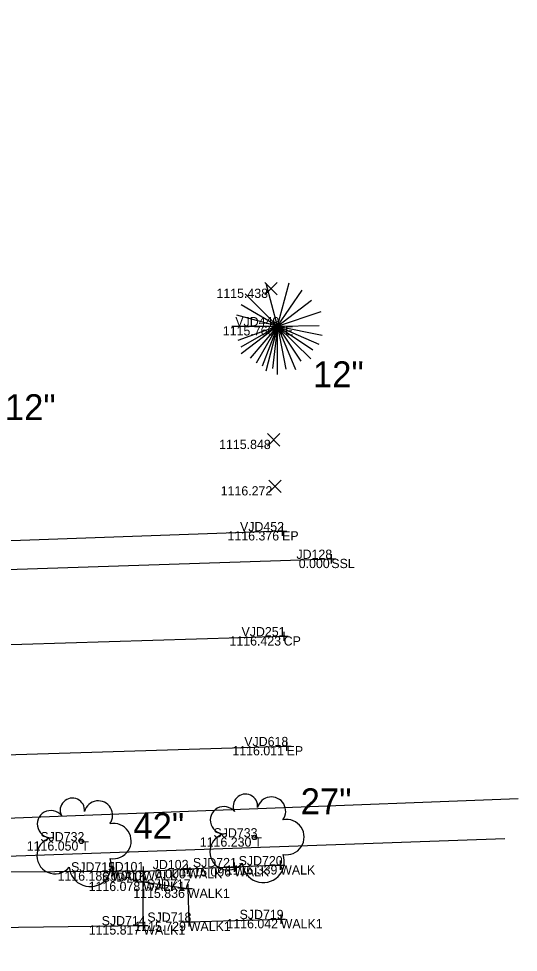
# Model space of a CAD drawing. Extents: x 1629915 to 1630675, y 484401 to 484601.
# Drawn here: x 1630621.1 to 1630675.1, y 484466.8 to 484567.8 of the extents above; entities that cross this region are included whole.
import ezdxf

# ---------------------------------------------------------------- set-up
doc = ezdxf.new("R2010")
doc.units = 0
for name, color, linetype in [('BR_X_Sub_Foot_Object', 7, 'Continuous'), ('PV_X_COP', 7, 'Continuous'), ('PV_X_EOP', 7, 'Continuous'), ('PV_X_Walk', 7, 'Continuous'), ('SV_X_Random_Point', 7, 'Continuous'), ('SV_X_Shot_Marker', 7, 'Continuous'), ('SV_X_Text_Comment', 7, 'Continuous'), ('SV_X_Text_Elevation', 7, 'Continuous'), ('SV_X_Text_Name', 7, 'Continuous'), ('TX_X_20', 7, 'Continuous'), ('UT_X_Sanitary_Line', 7, 'Continuous'), ('UT_X_Water', 7, 'Continuous'), ('VG_X_Cells', 7, 'Continuous')]:
    doc.layers.add(name, color=color, linetype=linetype)

msp = doc.modelspace()

# ---------------------------------------------------------------- linework, layer by layer
at = {"layer": 'BR_X_Sub_Foot_Object'}
msp.add_line((1630537.67, 484474.32), (1630673.62, 484479.09), dxfattribs=at)
at = {"layer": 'PV_X_COP'}
msp.add_lwpolyline([(1630297.37, 484489.97), (1630308.55, 484490.49), (1630361.84, 484492.4), (1630403.57, 484493.66), (1630440.46, 484494.93), (1630486.15, 484496.21), (1630529.23, 484497.46), (1630568.33, 484498.48), (1630611.93, 484499.83), (1630649.71, 484500.97)], dxfattribs=at)
at = {"layer": 'PV_X_EOP'}
for points in [[(1630649.54, 484512.34), (1630611.09, 484510.96), (1630568.31, 484509.62), (1630527.92, 484508.55), (1630486.05, 484507.69), (1630439.97, 484506.41), (1630403.1, 484505.48), (1630361.88, 484504.43), (1630301.74, 484502.19)], [(1630292.71, 484478.56), (1630303.89, 484478.68), (1630360.91, 484480.85), (1630403.55, 484482.24), (1630442.06, 484483.47), (1630486.34, 484484.8), (1630529.42, 484485.73), (1630568.75, 484486.75), (1630610.18, 484487.85), (1630650.03, 484489.09)]]:
    msp.add_lwpolyline(points, dxfattribs=at)
at = {"layer": 'PV_X_Walk'}
for p, q in [((1630631.16, 484475.53), (1630615.21, 484475.41)), ((1630634.52, 484475.56), (1630631.16, 484475.53)), ((1630644.35, 484475.99), (1630639.29, 484475.78))]:
    msp.add_line(p, q, dxfattribs=at)
for points in [[(1630634.52, 484475.56), (1630639.29, 484475.78)], [(1630649.33, 484476.2), (1630644.35, 484475.99)], [(1630493.48, 484465.78), (1630510.56, 484466.34), (1630535.88, 484467.05), (1630568.89, 484467.94), (1630595.48, 484468.58), (1630612.29, 484469.28), (1630612.76, 484463.55), (1630612.78, 484463.44), (1630611.46, 484463.36), (1630611.74, 484459.19), (1630617.57, 484459.66), (1630617.01, 484463.77), (1630616.02, 484463.69), (1630615.97, 484463.78), (1630615.61, 484469.43), (1630634.53, 484469.7), (1630634.52, 484474.41), (1630639.35, 484473.67), (1630639.45, 484470.09), (1630649.39, 484470.38)]]:
    msp.add_lwpolyline(points, dxfattribs=at)
at = {"layer": 'SV_X_Random_Point'}
for p, q in [((1630647.67, 484537.91), (1630649.01, 484539.24)), ((1630647.67, 484539.24), (1630649.01, 484537.91)), ((1630647.96, 484521.56), (1630649.29, 484522.9)), ((1630647.96, 484522.9), (1630649.29, 484521.56)), ((1630648.1, 484516.54), (1630649.44, 484517.88)), ((1630648.1, 484517.88), (1630649.44, 484516.54))]:
    msp.add_line(p, q, dxfattribs=at)
at = {"layer": 'SV_X_Shot_Marker'}
for p, q in [((1630649.54, 484512.84), (1630649.54, 484511.84)), ((1630649.04, 484512.34), (1630650.04, 484512.34)), ((1630649.54, 484512.34), (1630649.54, 484512.34)), ((1630654.86, 484509.85), (1630654.86, 484508.85)), ((1630654.36, 484509.35), (1630655.36, 484509.35)), ((1630654.86, 484509.35), (1630654.86, 484509.35)), ((1630649.21, 484500.97), (1630650.21, 484500.97)), ((1630649.71, 484501.47), (1630649.71, 484500.47)), ((1630649.71, 484500.97), (1630649.71, 484500.97)), ((1630650.03, 484489.59), (1630650.03, 484488.59)), ((1630649.53, 484489.09), (1630650.53, 484489.09)), ((1630650.03, 484489.09), (1630650.03, 484489.09)), ((1630644.35, 484476.49), (1630644.35, 484475.49)), ((1630649.33, 484476.7), (1630649.33, 484475.7)), ((1630630.66, 484475.53), (1630631.66, 484475.53)), ((1630631.16, 484476.03), (1630631.16, 484475.03)), ((1630631.16, 484475.53), (1630631.16, 484475.53)), ((1630634.02, 484475.56), (1630635.02, 484475.56)), ((1630634.52, 484476.06), (1630634.52, 484475.06)), ((1630634.52, 484475.56), (1630634.52, 484475.56)), ((1630638.79, 484475.78), (1630639.79, 484475.78)), ((1630639.29, 484476.28), (1630639.29, 484475.28)), ((1630639.29, 484475.78), (1630639.29, 484475.78)), ((1630643.85, 484475.99), (1630644.85, 484475.99)), ((1630644.35, 484475.99), (1630644.35, 484475.99)), ((1630648.83, 484476.2), (1630649.83, 484476.2)), ((1630649.33, 484476.2), (1630649.33, 484476.2)), ((1630634.02, 484474.41), (1630635.02, 484474.41)), ((1630634.52, 484474.91), (1630634.52, 484473.91)), ((1630634.52, 484474.41), (1630634.52, 484474.41)), ((1630638.85, 484473.67), (1630639.85, 484473.67)), ((1630639.35, 484474.17), (1630639.35, 484473.17)), ((1630639.35, 484473.67), (1630639.35, 484473.67)), ((1630639.45, 484470.59), (1630639.45, 484469.59)), ((1630648.89, 484470.38), (1630649.89, 484470.38)), ((1630649.39, 484470.88), (1630649.39, 484469.88)), ((1630649.39, 484470.38), (1630649.39, 484470.38)), ((1630634.03, 484469.7), (1630635.03, 484469.7)), ((1630634.53, 484470.2), (1630634.53, 484469.2)), ((1630634.53, 484469.7), (1630634.53, 484469.7)), ((1630638.95, 484470.09), (1630639.95, 484470.09)), ((1630639.45, 484470.09), (1630639.45, 484470.09))]:
    msp.add_line(p, q, dxfattribs=at)
at = {"layer": 'UT_X_Sanitary_Line'}
msp.add_lwpolyline([(1629930.75, 484483.73), (1630048.13, 484488.31), (1630252.72, 484494.6), (1630261.76, 484567.79), (1630373.42, 484500.09), (1630654.86, 484509.35)], dxfattribs=at)
at = {"layer": 'UT_X_Water'}
msp.add_line((1630348.22, 484470.93), (1630675.08, 484483.41), dxfattribs=at)
at = {"layer": 'VG_X_Cells'}
for p, q in [((1630649.04, 484534.52), (1630647.81, 484539.13)), ((1630649.04, 484534.52), (1630650.3, 484539.22)), ((1630649.04, 484534.52), (1630645.55, 484538.01)), ((1630649.04, 484534.52), (1630651.7, 484538.41)), ((1630649.04, 484534.52), (1630652.7, 484537.33)), ((1630649.04, 484534.52), (1630645.13, 484536.82)), ((1630649.04, 484534.52), (1630653.78, 484536.13)), ((1630649.04, 484534.52), (1630644.63, 484535.7)), ((1630644.11, 484534.52), (1630649.04, 484534.52)), ((1630649.04, 484534.52), (1630644.75, 484532.96)), ((1630649.04, 484534.52), (1630645.06, 484532.24)), ((1630649.04, 484534.52), (1630645.13, 484531.53)), ((1630649.04, 484534.52), (1630646.1, 484531.05)), ((1630649.04, 484534.52), (1630646.72, 484530.51)), ((1630649.04, 484534.52), (1630647.38, 484530.18)), ((1630649.04, 484534.52), (1630647.78, 484529.66)), ((1630649.04, 484534.52), (1630648.5, 484529.93)), ((1630649.04, 484534.52), (1630653.55, 484534.61)), ((1630649.04, 484529.28), (1630649.04, 484534.52)), ((1630649.04, 484534.52), (1630649.96, 484529.88)), ((1630649.04, 484534.52), (1630650.97, 484529.85)), ((1630649.04, 484534.52), (1630651.58, 484530.73)), ((1630649.04, 484534.52), (1630652.63, 484531)), ((1630649.04, 484534.52), (1630652.86, 484531.97)), ((1630649.04, 484534.52), (1630653.51, 484532.58)), ((1630649.04, 484534.52), (1630653.87, 484533.56))]:
    msp.add_line(p, q, dxfattribs=at)
for centre in [(1630646.55, 484479.21), (1630627.84, 484478.79)]:
    msp.add_circle(centre, 0.24, dxfattribs=at)
for centre, radius, start, end in [((1630626.86, 484482.15), 1.32, 354.0047, 205.9741), ((1630645.57, 484482.58), 1.32, 354.0047, 205.9741), ((1630648.38, 484482.04), 1.55, 323.83, 165.0376), ((1630629.67, 484481.62), 1.55, 323.83, 165.0376), ((1630643.24, 484481.08), 1.47, 39.0625, 279.5412), ((1630624.54, 484480.65), 1.47, 39.0625, 279.5412), ((1630631.31, 484478.82), 1.91, 259.1453, 101.4596), ((1630650.01, 484479.25), 1.91, 259.1453, 101.4596), ((1630643.7, 484477.66), 1.97, 96.1722, 320.5737), ((1630624.99, 484477.24), 1.97, 96.1722, 320.5737), ((1630647.5, 484476.61), 2.28, 184.9476, 19.4572), ((1630628.79, 484476.18), 2.28, 184.9476, 19.4572)]:
    msp.add_arc(centre, radius, start, end, dxfattribs=at)

# ---------------------------------------------------------------- texts
at = {"layer": 'SV_X_Text_Comment'}
for s, p in [('TE', (1630649.04, 484533.52)), ('EP', (1630649.54, 484511.34)), ('SSL', (1630654.86, 484508.35)), ('CP', (1630649.71, 484499.97)), ('EP', (1630650.03, 484488.09)), ('T', (1630627.84, 484477.79)), ('T', (1630646.55, 484478.21)), ('WALK', (1630631.16, 484474.53)), ('WALK', (1630634.52, 484474.56)), ('WALK', (1630639.29, 484474.78)), ('WALK', (1630644.35, 484474.99)), ('WALK', (1630649.33, 484475.2)), ('WALK1', (1630634.52, 484473.41)), ('WALK1', (1630639.35, 484472.67)), ('WALK1', (1630649.39, 484469.38)), ('WALK1', (1630634.53, 484468.7)), ('WALK1', (1630639.45, 484469.09))]:
    msp.add_text(s, height=1, dxfattribs=at).set_placement(p)
at = {"layer": 'SV_X_Text_Elevation'}
for s, p in [('1115.438', (1630642.44, 484537.58)), ('1115.760', (1630643.13, 484533.52)), ('1115.848', (1630642.73, 484521.23)), ('1116.272', (1630642.9, 484516.21)), ('1116.376', (1630643.64, 484511.34)), ('0.000', (1630651.34, 484508.35)), ('1116.423', (1630643.85, 484499.97)), ('1116.011', (1630644.16, 484488.09)), ('1116.050', (1630621.93, 484477.79)), ('1116.230', (1630640.64, 484478.21)), ('1116.186', (1630625.26, 484474.53)), ('0.000', (1630631, 484474.56)), ('0.000', (1630635.78, 484474.78)), ('1116.096', (1630638.45, 484474.99)), ('1116.339', (1630643.45, 484475.2)), ('1116.078', (1630628.62, 484473.41)), ('1115.836', (1630633.45, 484472.67)), ('1116.042', (1630643.52, 484469.38)), ('1115.817', (1630628.63, 484468.7)), ('1115.729', (1630633.56, 484469.09))]:
    msp.add_text(s, height=1, dxfattribs=at).set_placement(p)
at = {"layer": 'SV_X_Text_Name'}
for s, p in [('VJD449', (1630644.48, 484534.52)), ('VJD452', (1630644.99, 484512.34)), ('JD128', (1630651.09, 484509.35)), ('VJD251', (1630645.15, 484500.97)), ('VJD618', (1630645.45, 484489.09)), ('SJD732', (1630623.4, 484478.79)), ('SJD733', (1630642.12, 484479.21)), ('SJD715', (1630626.72, 484475.53)), ('JD101', (1630630.77, 484475.56)), ('JD102', (1630635.55, 484475.78)), ('SJD721', (1630639.89, 484475.99)), ('SJD720', (1630644.84, 484476.2)), ('SJD716', (1630630.04, 484474.41)), ('SJD717', (1630634.88, 484473.67)), ('SJD719', (1630644.94, 484470.38)), ('SJD714', (1630630.03, 484469.7)), ('SJD718', (1630634.97, 484470.09))]:
    msp.add_text(s, height=1, dxfattribs=at).set_placement(p)
at = {"layer": 'TX_X_20'}
for s, p in [('12"', (1630652.87, 484527.92)), ('12"', (1630619.56, 484524.36)), ('27"', (1630651.55, 484481.72)), ('42"', (1630633.46, 484479.06))]:
    msp.add_text(s, height=2.8, dxfattribs=at).set_placement(p)

doc.saveas('drawing.dxf')
